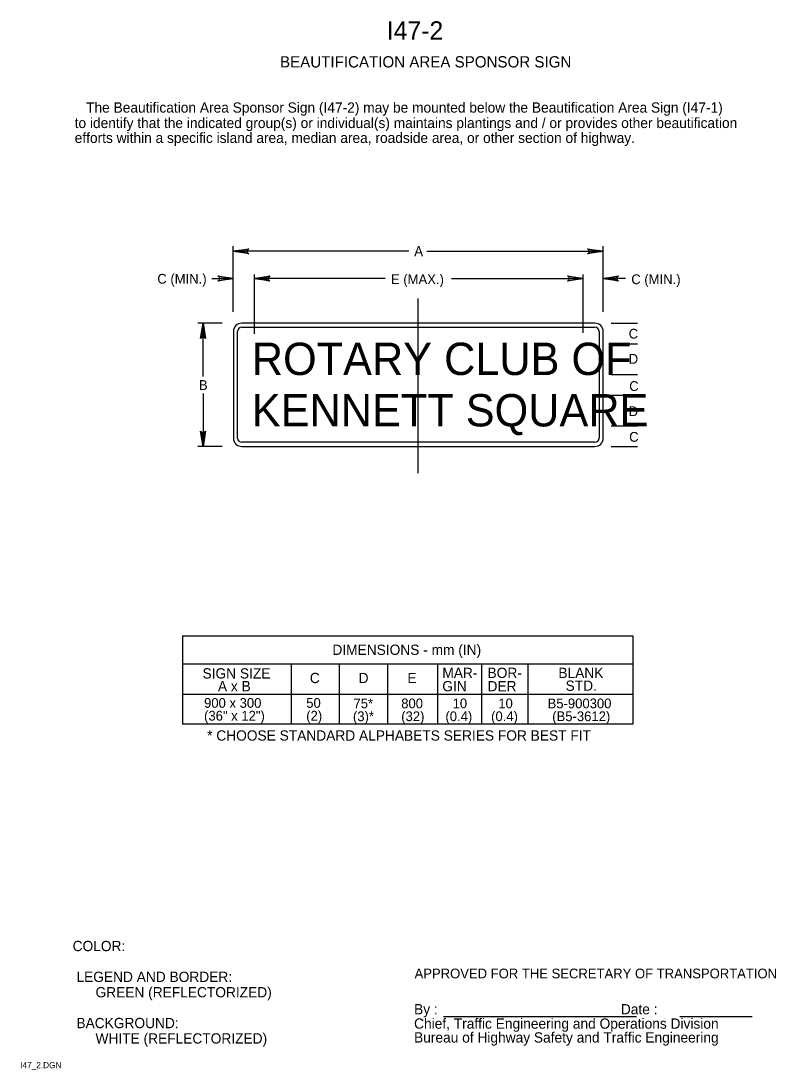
# Model space of a CAD drawing. Extents: x 0.013 to 0.196, y 0.004 to 0.259.
import ezdxf

# ---------------------------------------------------------------- set-up
doc = ezdxf.new("R2010")
doc.units = 0
for name, color, linetype in [('Level 1', 7, 'Continuous'), ('Level 2', 7, 'Continuous'), ('Level 3', 7, 'Continuous')]:
    doc.layers.add(name, color=color, linetype=linetype)

# ---------------------------------------------------------------- blocks, each defined once
blk = doc.blocks.new('RARROW')
at = {"layer": 'Level 3'}
for p, q in [((-2.156, 0.285), (-2.2665, 0.384625)), ((-2.2665, 0.384625), (0, 0)), ((0, 0), (-2.2665, -0.379125)), ((-2.156, 0.285), (-2.075625, 0.12075)), ((0, 0), (-2.156, 0.285)), ((-2.14975, -0.2705), (0, 0)), ((-2.075625, 0.12075), (0, 0)), ((0, 0), (-2.074, -0.108)), ((-2.2665, -0.379125), (-2.14975, -0.2705)), ((-2.074, -0.108), (-2.14975, -0.2705))]:
    blk.add_line(p, q, dxfattribs=at)

msp = doc.modelspace()

# ---------------------------------------------------------------- linework, layer by layer
at = {"layer": 'Level 1'}
for p, q in [((0.11544, 0.01695), (0.16242, 0.01695)), ((0.17295, 0.01695), (0.19056, 0.01695))]:
    msp.add_line(p, q, dxfattribs=at)
at = {"layer": 'Level 3'}
for p, q in [((0.06425, 0.1885), (0.06425, 0.2045)), ((0.15425, 0.1885), (0.15425, 0.2045)), ((0.107, 0.20325), (0.06425, 0.20325)), ((0.11138, 0.20325), (0.15425, 0.20325)), ((0.06938, 0.18313), (0.06938, 0.19762)), ((0.14938, 0.18338), (0.14938, 0.19762)), ((0.059, 0.19662), (0.06425, 0.19662)), ((0.07337, 0.19662), (0.06938, 0.19662)), ((0.10125, 0.19662), (0.06938, 0.19662)), ((0.11738, 0.19662), (0.14938, 0.19662)), ((0.15975, 0.19662), (0.15425, 0.19662)), ((0.10925, 0.14925), (0.10925, 0.19175)), ((0.0615, 0.18575), (0.05563, 0.18575)), ((0.05688, 0.17275), (0.05688, 0.18575)), ((0.15229, 0.18575), (0.06629, 0.18575)), ((0.06629, 0.18475), (0.15229, 0.18475)), ((0.15625, 0.18575), (0.16262, 0.18575)), ((0.06429, 0.18375), (0.06429, 0.15775)), ((0.06529, 0.15775), (0.06529, 0.18375)), ((0.15329, 0.18375), (0.15329, 0.15775)), ((0.15429, 0.15775), (0.15429, 0.18375)), ((0.15625, 0.18075), (0.16262, 0.18075)), ((0.15625, 0.17325), (0.16262, 0.17325)), ((0.05688, 0.16862), (0.05688, 0.15575)), ((0.15625, 0.16825), (0.16262, 0.16825)), ((0.15625, 0.16075), (0.16262, 0.16075)), ((0.15229, 0.15675), (0.06629, 0.15675)), ((0.0615, 0.15575), (0.05563, 0.15575)), ((0.06629, 0.15575), (0.15229, 0.15575)), ((0.15625, 0.15575), (0.16262, 0.15575)), ((0.05188, 0.10963), (0.1615, 0.10963)), ((0.05188, 0.10963), (0.05188, 0.08812)), ((0.16154, 0.10962), (0.16154, 0.08812)), ((0.1615, 0.10275), (0.05188, 0.10275)), ((0.07829, 0.10275), (0.07829, 0.08812)), ((0.09, 0.10275), (0.09, 0.08812)), ((0.10175, 0.10275), (0.10175, 0.08812)), ((0.11392, 0.10275), (0.11392, 0.08812)), ((0.12467, 0.10275), (0.12467, 0.08812)), ((0.13596, 0.10275), (0.13596, 0.08812)), ((0.1615, 0.09538), (0.05188, 0.09538)), ((0.1615, 0.08812), (0.05188, 0.08812))]:
    msp.add_line(p, q, dxfattribs=at)
for centre, radius, start, end in [((0.06629, 0.18375), 0.002, 90, 180), ((0.06629, 0.18375), 0.001, 90, 180), ((0.15229, 0.18375), 0.002, 0, 90), ((0.15229, 0.18375), 0.001, 0, 90), ((0.06629, 0.15775), 0.002, 180, 270), ((0.06629, 0.15775), 0.001, 180, 270), ((0.15229, 0.15775), 0.002, 270, 0), ((0.15229, 0.15775), 0.001, 270, 0)]:
    msp.add_arc(centre, radius, start, end, dxfattribs=at)

# ---------------------------------------------------------------- block references
at = {"layer": 'Level 3', "xscale": 0.0016545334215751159, "yscale": 0.0016366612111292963}
for p, rotation in [((0.06425, 0.20325), 180), ((0.06938, 0.19662), 180), ((0.15425, 0.19662), 180), ((0.05688, 0.18575), 90), ((0.05688, 0.15575), -90)]:
    msp.add_blockref('RARROW', p, dxfattribs=dict(at, rotation=rotation))
for p in [(0.15425, 0.20325), (0.06425, 0.19662), (0.14938, 0.19662)]:
    msp.add_blockref('RARROW', p, dxfattribs=at)

# ---------------------------------------------------------------- texts
at = {"layer": 'Level 1'}
for s, height, p in [('I47-2', 0.0045, (0.10163, 0.25475)), ('BEAUTIFICATION AREA SPONSOR SIGN', 0.0027503, (0.07562, 0.248)), ('COLOR:', 0.0025, (0.02513, 0.03288)), ('APPROVED FOR THE SECRETARY OF TRANSPORTATION', 0.0023752, (0.10837, 0.02625)), (' LEGEND AND BORDER:', 0.0024998, (0.02513, 0.02538)), ('      GREEN (REFLECTORIZED)', 0.0024998, (0.02513, 0.02163)), ('By :                                                Date :', 0.0024998, (0.10825, 0.0175)), (' BACKGROUND:', 0.0024998, (0.02513, 0.01413)), ('Chief, Traffic Engineering and Operations Division', 0.0024998, (0.10825, 0.014)), ('      WHITE (REFLECTORIZED)', 0.0024998, (0.02513, 0.01038)), ('Bureau of Highway Safety and Traffic Engineering', 0.0024998, (0.10825, 0.01063)), ('I47_2.DGN', 0.0015, (0.01238, 0.00438))]:
    msp.add_text(s, height=height, dxfattribs=at).set_placement(p)
at = {"layer": 'Level 2'}
for s, height, p in [('   The Beautification Area Sponsor Sign (I47-2) may be mounted below the Beautification Area Sign (I47-1)', 0.00249975, (0.02563, 0.237)), ('to identify that the indicated group(s) or individual(s) maintains plantings and / or provides other beautification', 0.00249975, (0.02563, 0.23325)), ('efforts within a specific island area, median area, roadside area, or other section of highway.', 0.0024998, (0.02563, 0.22962))]:
    msp.add_text(s, height=height, dxfattribs=at).set_placement(p)
at = {"layer": 'Level 3'}
for s, height, p in [('A', 0.0025, (0.10825, 0.202)), ('C (MIN.)', 0.002375, (0.04575, 0.19537)), ('E (MAX.)', 0.002375, (0.10263, 0.19525)), ('C (MIN.)', 0.002375, (0.16112, 0.19525)), ('C', 0.00238, (0.1605, 0.182)), ('ROTARY CLUB OF', 0.0078742, (0.06875, 0.17313)), ('D', 0.00238, (0.1605, 0.17588)), ('B', 0.00238, (0.05588, 0.1695)), ('C', 0.00238, (0.16062, 0.16925)), ('KENNETT SQUARE', 0.007875, (0.06875, 0.16062)), ('D', 0.00238, (0.1605, 0.16312)), ('C', 0.00238, (0.16062, 0.15688)), ('DIMENSIONS - mm (IN)', 0.0024998, (0.08837, 0.105)), ('SIGN SIZE', 0.0025, (0.05675, 0.09925)), ('C', 0.0025, (0.08288, 0.09813)), ('D', 0.0025, (0.09475, 0.09813)), ('E', 0.0025, (0.10662, 0.09813)), ('MAR-', 0.0025, (0.11513, 0.09938)), ('BOR-', 0.0025, (0.12613, 0.09938)), ('BLANK', 0.0025, (0.14338, 0.09938)), ('A x B', 0.0025, (0.0605, 0.09613)), ('GIN', 0.0025, (0.11513, 0.09613)), ('DER', 0.0025, (0.12613, 0.09613)), ('STD.', 0.0025, (0.14513, 0.09625)), ('900 x 300', 0.002375, (0.05713, 0.09212)), ('50', 0.002375, (0.082, 0.09212)), ('75*', 0.002375, (0.0935, 0.092)), ('800', 0.002375, (0.10512, 0.092)), ('10', 0.002375, (0.11763, 0.092)), ('10', 0.002375, (0.12875, 0.092)), ('B5-900300', 0.002375, (0.14075, 0.092)), ('(36" x 12")', 0.0023752, (0.05713, 0.089)), ('(2)', 0.002375, (0.082, 0.089)), ('(3)*', 0.002375, (0.09337, 0.08887)), ('(32)', 0.002375, (0.10512, 0.08887)), ('(0.4)', 0.002375, (0.11588, 0.08887)), ('(0.4)', 0.002375, (0.127, 0.08887)), ('(B5-3612)', 0.002375, (0.14188, 0.08887)), ('* CHOOSE STANDARD ALPHABETS SERIES FOR BEST FIT', 0.0024998, (0.05788, 0.08413))]:
    msp.add_text(s, height=height, dxfattribs=at).set_placement(p)

doc.saveas('drawing.dxf')
